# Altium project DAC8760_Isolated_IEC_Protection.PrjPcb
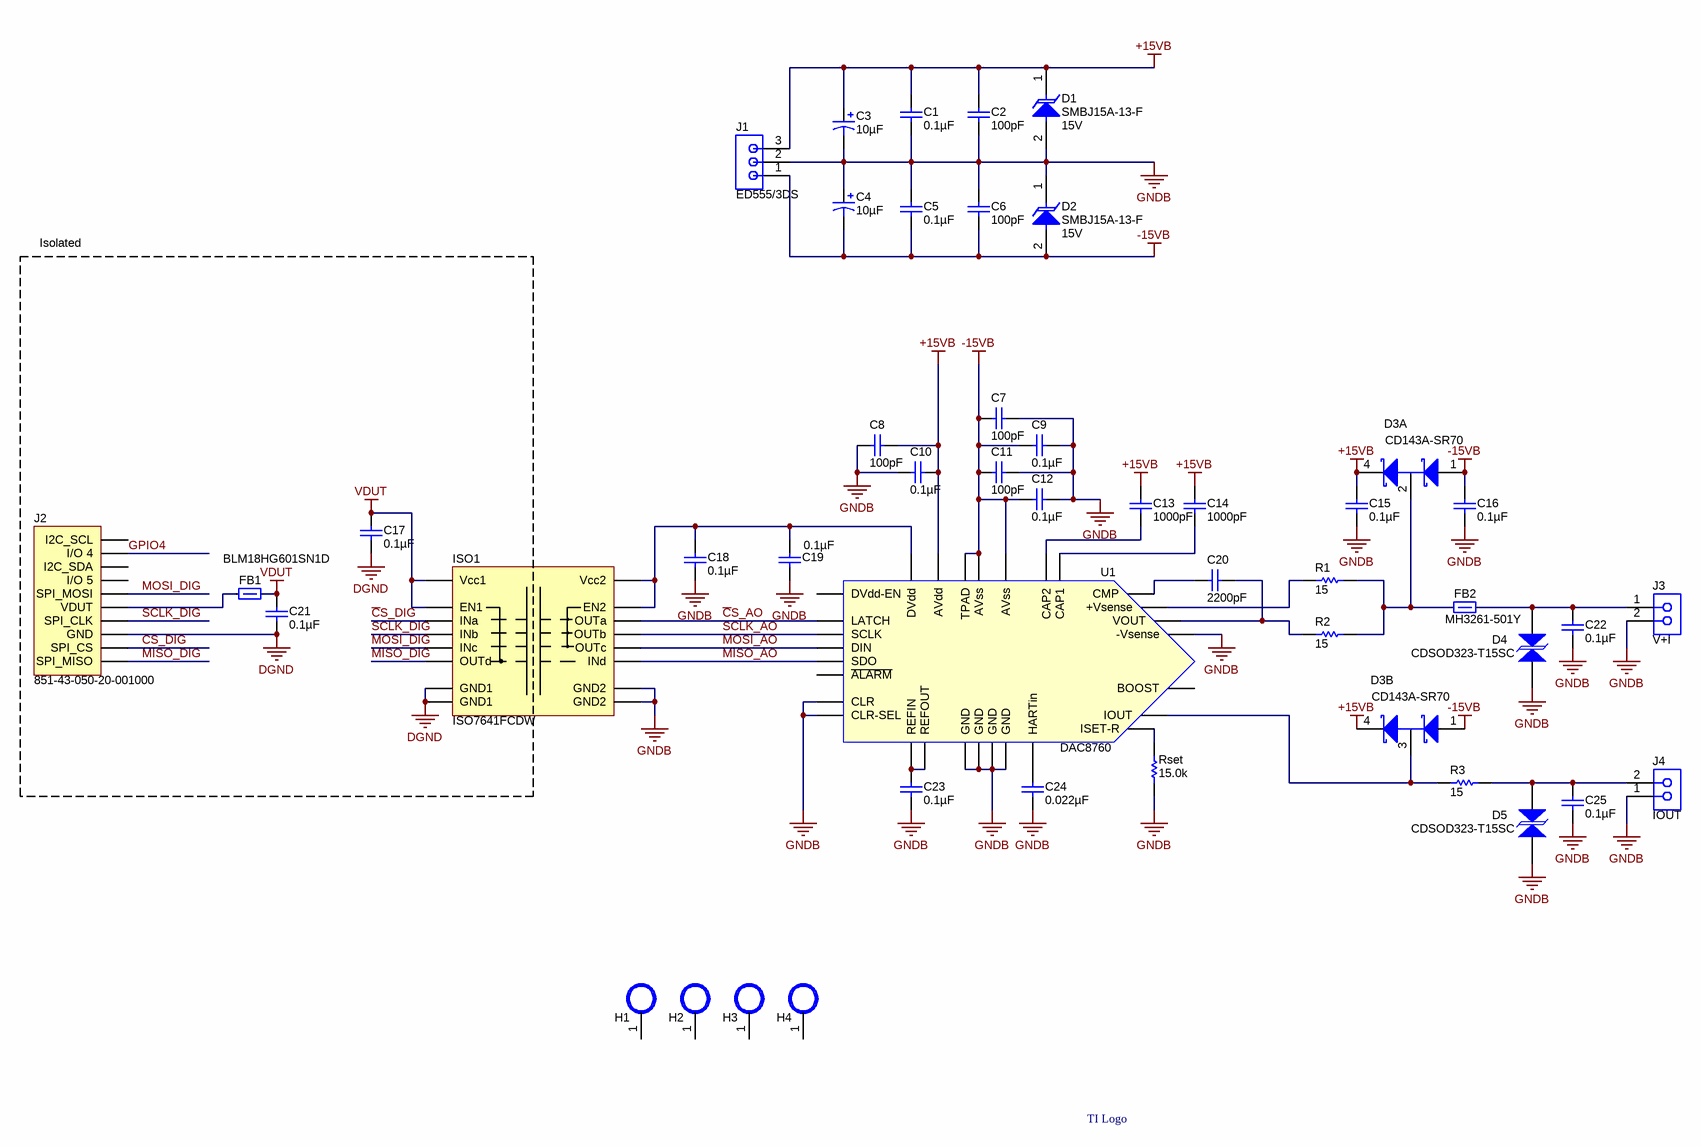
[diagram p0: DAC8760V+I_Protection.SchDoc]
CopyrightYear: 2012; PCB_CopperRev: 001; PCB_SilkRev: REV A; PRJ_Customer: TI Precision Designs; PRJ_Title: TIPD153 - Single-Channel Industrial Voltage and Current Output Driver; SCH_Rev: A; TechSupport: http://www.ti.com/support
1 sheet, 47 parts. Net scope: global (net labels, ports and power ports of the same name join across sheets).
Board file: DAC8760_V+I_Protection.PcbDoc

## Sheet DAC8760V+I_Protection.SchDoc: TIPD153
size 431 x 279 mm; Date: Not shown in title block; ApprovedBy: Not shown in title block; CheckedBy: Not shown in title block; Author: Not shown in title block; CompanyName: Not shown in title block; DrawnBy: Not shown in title block; Engineer: Not shown in title block; Organization: Not shown in title block; Address1: Not shown in title block; Address2: Not shown in title block; Address3: Not shown in title block; Address4: Not shown in title block; DocumentNumber: 1; Revision: Use project parameter SCH_Rev; SheetNumber: 1; SheetTotal: 1; PageSetup: Record=PageOptions|CenterHorizontal=True|CenterVertical=True|PrintScale=0.96|XCorrection=1.00|YCorrection=1.00|PrintKind=0|BorderSize=5000000|LeftOffset=0|BottomOffset=0|Orientation=2|PaperLength=1000|PaperWidth=1000|Scale=100|PaperSource=259|PrintQuality=600|MediaType=1|DitherType=10|PaperKind=11x17|PrintScaleMode=1

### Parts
C1  ValueDisplayed: 0.1µF  [0603]  (hidden comment: GRM188R71H104KA93D)
C2  ValueDisplayed: 100pF  [0603]  (hidden comment: 06035A101JAT2A)
C3  ValueDisplayed: 10µF  [7343-43]  (hidden comment: 293D106X9050E2TE3)
C4  ValueDisplayed: 10µF  [7343-43]  (hidden comment: 293D106X9050E2TE3)
C5  ValueDisplayed: 0.1µF  [0603]  (hidden comment: GRM188R71H104KA93D)
C6  ValueDisplayed: 100pF  [0603]  (hidden comment: 06035A101JAT2A)
C7  ValueDisplayed: 100pF  [0603]  (hidden comment: 06035A101JAT2A)
C8  ValueDisplayed: 100pF  [0603]  (hidden comment: 06035A101JAT2A)
C9  ValueDisplayed: 0.1µF  [0603]  (hidden comment: GRM188R71H104KA93D)
C10  ValueDisplayed: 0.1µF  [0603]  (hidden comment: GRM188R71H104KA93D)
C11  ValueDisplayed: 100pF  [0603]  (hidden comment: 06035A101JAT2A)
C12  ValueDisplayed: 0.1µF  [0603]  (hidden comment: GRM188R71H104KA93D)
C13  ValueDisplayed: 1000pF  [0603]  (hidden comment: GRM188R72A102KA01D)
C14  ValueDisplayed: 1000pF  [0603]  (hidden comment: GRM188R72A102KA01D)
C15  ValueDisplayed: 0.1µF  [0603]  (hidden comment: GRM188R71H104KA93D)
C16  ValueDisplayed: 0.1µF  [0603]  (hidden comment: GRM188R71H104KA93D)
C17  ValueDisplayed: 0.1µF  [0603]  (hidden comment: GRM188R71H104KA93D)
C18  ValueDisplayed: 0.1µF  [0603]  (hidden comment: GRM188R71H104KA93D)
C19  ValueDisplayed: 0.1µF  [0603]  (hidden comment: GRM188R71H104KA93D)
C20  ValueDisplayed: 2200pF  [0603]  (hidden comment: GRM1885C1H222JA01D)
C21  ValueDisplayed: 0.1µF  [0603]  (hidden comment: GRM188R71H104KA93D)
C22  ValueDisplayed: 0.1µF  [0603]  (hidden comment: 06035C104KAT2A)
C23  ValueDisplayed: 0.1µF  [0603]  (hidden comment: 06035C104KAT2A)
C24  ValueDisplayed: 0.022µF  [0603]  (hidden comment: C1608X7R1H223K)
C25  ValueDisplayed: 0.1µF  [0603]  (hidden comment: 06035C104KAT2A)
D1  SMBJ15A-13-F  value 15V  [SMB]
D2  SMBJ15A-13-F  value 15V  [SMB]
D3  CD143A-SR70  [SOT-143]  (parts A,B of 2)
D4  CDSOD323-T15SC  [sod-323]
D5  CDSOD323-T15SC  [sod-323]
FB1  BLM18HG601SN1D  [0603]
FB2  MH3261-501Y  [1210]
H1  NA  [Mounting Hole]  (value not drawn)  (no BOM)
H2  NA  [Mounting Hole]  (value not drawn)  (no BOM)
H3  NA  [Mounting Hole]  (value not drawn)  (no BOM)
H4  NA  [Mounting Hole]  (value not drawn)  (no BOM)
ISO1  ISO7641FCDW  [M16B_N]
J1  ED555/3DS  [ED555/3DS]
J2  851-43-050-20-001000  [851-43-010-20-001000]
J3  V+I  [ED555/2DS]
J4  IOUT  [ED555/2DS]
R1  value 15  [0603]  (hidden comment: CRCW060315R0JNEA)
R2  value 15  [0603]  (hidden comment: CRCW060315R0JNEA)
R3  value 15  [1210]  (hidden comment: RPC2512JT15R0)
Rset  value 15.0k  [0603]  (hidden comment: RT0603BRD0715KL)
TI1  Texas Instruments logo  [TI LOGO]  (value not drawn)  (no BOM)
U1  DAC8760  [SQA40A]

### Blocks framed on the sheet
Isolated: C17 C21 FB1 J2

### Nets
+15VB: C1.2 C2.1 C3.1(+) C8.1 C10.1 C13.1 C14.1 C15.1 D1.1(K) D3.4 J1.3 U1.36(AVdd)
-15VB: C4.2(-) C5.1 C6.2 C7.2 C9.2 C11.2 C12.2 C16.1 D2.2(A) D3.1 J1.1 U1.14(AVss) U1.37(AVss) U1.41(TPAD)
DGND: C17.2 C21.2 ISO1.2(GND1) ISO1.8(GND1) J2.8(GND)
GNDB: C1.1 C2.2 C3.2(-) C4.1(+) C5.2 C6.1 C7.1 C8.2 C9.1 C10.2 C11.1 C12.1 C15.2 C16.2 C18.2 C19.2 C22.2 C23.2 C24.2 C25.2 D1.2(A) D2.1(K) D4.2 D5.2 ISO1.9(GND2) ISO1.15(GND2) J1.2 J3.2 J4.1 Rset.1 U1.3(GND) U1.4(CLR-SEL) U1.5(CLR) U1.12(GND) U1.13(GND) U1.15(GND) U1.34(-Vsense)
VDUT: C17.1 C21.1 FB1.2 ISO1.1(Vcc1) ISO1.7(EN1)
~{C}S_AO: ISO1.14(OUTa) U1.6(LATCH)
~{C}S_DIG: ISO1.3(INa) J2.9(SPI_CS)
GPIO4: J2.2(I/O_4)
MISO_AO: ISO1.11(INd) U1.9(SDO)
MISO_DIG: ISO1.6(OUTd) J2.10(SPI_MISO)
MOSI_AO: ISO1.12(OUTc) U1.8(DIN)
MOSI_DIG: ISO1.5(INc) J2.5(SPI_MOSI)
SCLK_AO: ISO1.13(OUTb) U1.7(SCLK)
SCLK_DIG: ISO1.4(INb) J2.7(SPI_CLK)
NetC13_2: C13.2 U1.29(CAP2)
NetC14_2: C14.2 U1.28(CAP1)
NetC18_1: C18.1 C19.1 ISO1.10(EN2) ISO1.16(Vcc2) U1.39(DVdd)
NetC20_1: C20.1 R2.1 U1.32(VOUT)
NetC20_2: C20.2 U1.24(CMP)
NetC22_1: C22.1 D4.1 FB2.2 J3.1
NetC23_1: C23.1 U1.17(REFOUT) U1.18(REFIN)
NetC24_1: C24.1 U1.25(HARTin)
NetC25_1: C25.1 D5.1 J4.2 R3.2
NetD3_2: D3.2 FB2.1 R1.2 R2.2
NetD3_3: D3.3 R3.1 U1.26(IOUT)
NetFB1_1: FB1.1 J2.6(VDUT)
NetR1_1: R1.1 U1.33(+Vsense)
NetRset_2: Rset.2 U1.16(ISET-R)

Not connected (* = marked no-connect by the designer): H1 1; H2 1; H3 1; H4 1; J2 1(I2C_SCL) 3(I2C_SDA) 4(I/O_5); U1 1(NC) 2(~{ALARM}) 10(NC) 11(NC) 19(NC) 20(NC) 21(NC) 22(NC) 23(DVdd-EN) 27(BOOST) 30(NC) 31(NC) 35(NC) 38(NC) 40(NC)

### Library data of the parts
C1 C5 C9 C10 C12 C15-C19 C21 = GRM188R71H104KA93D: CAP, CERM, 0.1uF, 50V, +/-10%, X7R, 0603; Manufacturer: MuRata; Polarized: N; CompType: Capacitor; U/M: EA; Cap_F: 0.0000001; Tolerance_%: 10; VDC_V: 50; TaMin_C: -55; TaMax_C: 125
C2 C6-C8 C11 = 06035A101JAT2A: CAP, CERM, 100pF, 50V, +/-5%, C0G/NP0, 0603; Manufacturer: AVX; Polarized: N; CompType: Capacitor; U/M: EA; Cap_F: 0.0000000001; Tolerance_%: 5; ESR_Ohm: 0.119; Value1: 0.119 ohm; VDC_V: 50; TaMin_C: -55; TaMax_C: 125
C3 C4 = 293D106X9050E2TE3: CAP, TANT, 10uF, 50V, +/-10%, 0.8 ohm, 7343-43 SMD; Manufacturer: Vishay-Sprague; Polarized: Y; CompType: Capacitor; U/M: EA; Cap_F: 0.00001; Tolerance_%: 10; Value1: 0.8 ohm; VDC_V: 50; ESR_Ohm: 0.8; IRMS_A: 0.45; TaMin_C: -55; TaMax_C: 125; Cap_Case: E
C13 C14 = GRM188R72A102KA01D: CAP, CERM, 1000pF, 100V, +/-10%, X7R, 0603; Manufacturer: MuRata; Polarized: N; CompType: Capacitor; U/M: EA; Cap_F: 0.000000001; Tolerance_%: 10; Value1: Unknown; VDC_V: 100; TaMin_C: -55; TaMax_C: 125
C20 = GRM1885C1H222JA01D: CAP, CERM, 2200pF, 50V, +/-5%, C0G/NP0, 0603; Manufacturer: MuRata; Polarized: N; CompType: Capacitor; U/M: EA; Cap_F: 0.0000000022; Tolerance_%: 5; Value1: Unknown; VDC_V: 50; TaMin_C: -55; TaMax_C: 125
C22 C23 C25 = 06035C104KAT2A: CAP, CERM, 0.1uF, 50V, +/-10%, X7R, 0603; Manufacturer: AVX; Polarized: N; CompType: Capacitor; U/M: EA; Cap_F: 0.0000001; Tolerance_%: 10; Value1: Unknown; VDC_V: 50; TaMin_C: -55; TaMax_C: 125
C24 = C1608X7R1H223K: CAP, CERM, 0.022uF, 50V, +/-10%, X7R, 0603; Manufacturer: TDK; Polarized: N; CompType: Capacitor; U/M: EA; Cap_F: 0.000000022; Tolerance_%: 10; ESR_Ohm: 0.0383; Value1: 0.0383 ohm; VDC_V: 50; TaMin_C: -55; TaMax_C: 125
D1 D2 = SMBJ15A-13-F: Diode, TVS, Uni, 15V, 600W, SMB; Manufacturer: Diodes Inc.; U/M: EA; Power_W: 5; Vr_V: 15; Value1: 5W
D3 = CD143A-SR70: IC TVS ARRAY 2-LINE 70V SOT-143; Manufacturer: Bourns; SymbolVersion: use current date i.e. 2008-05-20; SymbolCreator: Use LDAP id; U/M: EA, IN, or GM
D4 D5 = SMAJ15CA: DIODE TVS ARRAY 15V SOD323; Manufacturer: Bourns; SymbolVersion: use current date i.e. 2008-05-20; SymbolCreator: Use LDAP id; U/M: EA, IN, or GM
FB1 = Ferrite_Bead: FERRITE CHIP 600 OHM 200MA 0603; Manufacturer: MuRata; U/M: EA
FB2 = Ferrite_Bead: BEAD FERRITE 500 OHM 3.0A 3216; Manufacturer: Bourns Inc.; CompType: Resistor; U/M: EA
H1-H4 = Mounting Hole: Manufacturer: Used in BOM report; SymbolVersion: use current date i.e. 2008-05-20; SymbolCreator: Use LDAP id; CompType: Used in some BOM reports.  Useful for finding later.; U/M: EA, IN, or GM
ISO1 = ISO7241: ISOLATOR DGTL 25MBPS 4CH 16SOIC; Manufacturer: Texas Instruments Inc; SymbolVersion: use current date i.e. 2008-05-20; SymbolCreator: Use LDAP id; CompType: Used in some BOM reports.  Useful for finding later.; U/M: EA, IN, or GM
J1 = 1715734: TERMINAL BLOCK 3.5MM 3POS PCB; Manufacturer: On Shore Technology Inc; SymbolVersion: use current date i.e. 2008-05-20; SymbolCreator: Use LDAP id; U/M: EA, IN, or GM
J2 = SM-USB-DIG-CONN: CONN SOCKET 50PIN .050 R/A SNGL; Manufacturer: Mill-Max Manufacturing Corp.; SymbolCreator: Use LDAP id; U/M: EA, IN, or GM
J3 J4 = 1727010: TERMINAL BLOCK 3.5MM 2POS PCB; Manufacturer: On Shore Technology Inc; U/M: EA; Value: 2x1
R1 R2 = CRCW060315R0JNEA: RES, 15 ohm, 5%, 0.1W, 0603; Manufacturer: Vishay-Dale; CompType: Resistor; Value_Code: 15R0; Tolerance_%: 5; Power_W: 0.1; VDC_V: 75; TempCo: 200 ppm/C; EIA_Code: E24; U/M: EA
R3 = CRA2512-FZ-R080ELF: RES 15 OHM 1W 5% 2512; Manufacturer: Stackpole Electronics; CompType: Resistor; Value_Code: 15R; Tolerance_%: 5; Power_W: 3; VDC_V: 0; U/M: EA
Rset = RT0603BRD0715KL: RES, 15.0k ohm, 0.1%, 0.1W, 0603; Manufacturer: Yageo America; CompType: Resistor; Res_ohm: 15000; Value_Code: 15k0; Tolerance_%: 0.1; VDC_V: 75; TempCo: 25 ppm/C; EIA_Code: E192; U/M: EA
TI1 = TI LOGO: TI BUG
U1 = DAC8760: DAC8760 DAC-XTR RTA QFN-40; Manufacturer: Texas Instruments; SymbolVersion: use current date i.e. 2008-05-20; SymbolCreator: Use LDAP id; CompType: XTR; U/M: EA, IN, or GM

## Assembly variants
-100A: all parts fitted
